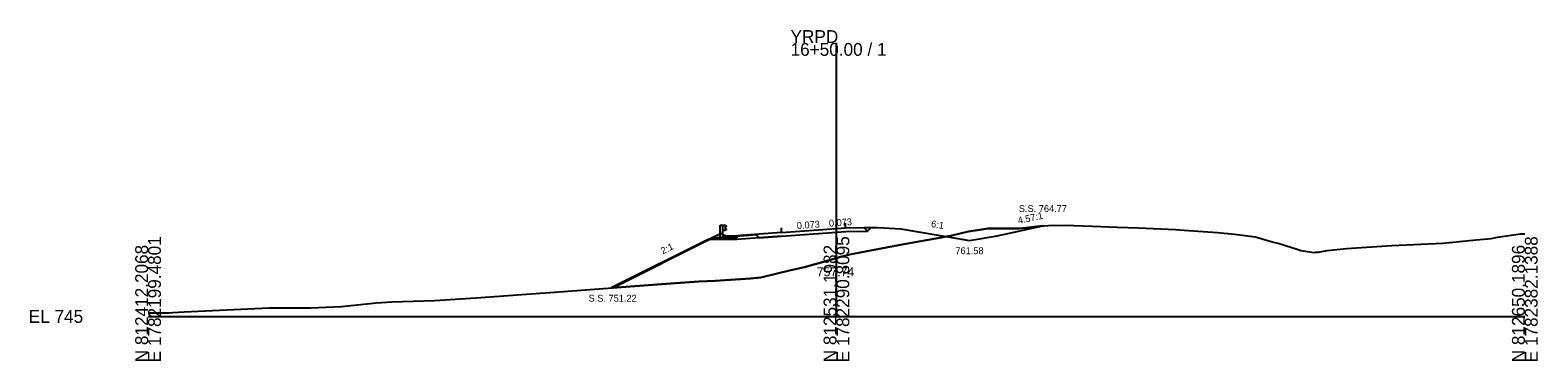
# Model space of a CAD drawing. Extents: x -26 to 1403, y -10 to 9544.
# Drawn here: x -25.7 to 302.8, y 6490.3 to 6562.4 of the extents above; entities that cross this region are included whole.
import ezdxf

# ---------------------------------------------------------------- set-up
doc = ezdxf.new("R2010")
doc.units = 0
for name, color, linetype in [('Exist Cross Section Cell', 7, 'Continuous'), ('Exist XS Center Line Elevation Label', 7, 'Continuous'), ('Exist XS Ground Line', 7, 'Continuous'), ('Prop XS Ditch Slope Text', 7, 'Continuous'), ('Prop XS Ditch Standard Text', 7, 'Continuous'), ('Prop XS Dump Level', 7, 'Continuous'), ('Prop XS Earthwork Shape', 7, 'Continuous'), ('Prop XS EOT Tick Mark', 7, 'Continuous'), ('Prop XS Finish Grade', 7, 'Continuous'), ('Prop XS Finish Grade CurbGutter', 7, 'Continuous'), ('Prop XS Finish Grade Earthwork', 7, 'Continuous'), ('Prop XS Finish Grade Paved Shoulder', 7, 'Continuous'), ('Prop XS Finish Grade Pavement', 7, 'Continuous'), ('Prop XS Guardrail', 7, 'Continuous'), ('Prop XS Pvmt Edge Slope', 7, 'Continuous'), ('Prop XS SE Text', 7, 'Continuous'), ('Prop XS Side Slope Text', 7, 'Continuous'), ('Prop XS SS Elevation Text', 7, 'Continuous'), ('Prop XS Subgrade CurbGutter', 7, 'Continuous'), ('Prop XS Subgrade Earthwork', 7, 'Continuous')]:
    doc.layers.add(name, color=color, linetype=linetype)

msp = doc.modelspace()

# ---------------------------------------------------------------- linework, layer by layer
at = {"layer": 'Exist Cross Section Cell'}
for p, q in [((150, 6500), (150, 6559.64)), ((0, 6500), (150, 6500)), ((150, 6500), (300, 6500))]:
    msp.add_line(p, q, dxfattribs=at)
at = {"layer": 'Exist XS Ground Line'}
for p, q in [((175.14, 6517.65), (178.79, 6518.55)), ((178.79, 6518.55), (181.71, 6518.99)), ((181.71, 6518.99), (183.02, 6519.2)), ((183.02, 6519.2), (188.84, 6519.19)), ((188.84, 6519.19), (189.82, 6519.21)), ((189.82, 6519.21), (190.64, 6519.27)), ((190.64, 6519.27), (195.21, 6519.79)), ((195.21, 6519.79), (196.23, 6519.81)), ((196.23, 6519.81), (199.73, 6519.88)), ((199.73, 6519.88), (205.83, 6519.68)), ((205.83, 6519.68), (211.19, 6519.49)), ((211.19, 6519.49), (215.84, 6519.29)), ((215.84, 6519.29), (223.87, 6518.96)), ((223.87, 6518.96), (224.75, 6518.9)), ((224.75, 6518.9), (227.83, 6518.69)), ((227.83, 6518.69), (233.06, 6518.29)), ((233.06, 6518.29), (236.75, 6517.91)), ((154.78, 6513.89), (164.35, 6515.71)), ((164.35, 6515.71), (173.7, 6517.35)), ((173.7, 6517.35), (175.14, 6517.65)), ((236.75, 6517.91), (241.29, 6517.36)), ((241.29, 6517.36), (244.96, 6516.27)), ((244.96, 6516.27), (246.46, 6515.94)), ((246.46, 6515.94), (250.4, 6514.65)), ((256.91, 6514.38), (261.14, 6514.82)), ((261.14, 6514.82), (271.01, 6515.46)), ((271.01, 6515.46), (282.12, 6515.99)), ((282.12, 6515.99), (289.37, 6516.69)), ((289.37, 6516.69), (292.66, 6516.99)), ((292.66, 6516.99), (294.07, 6517.26)), ((294.07, 6517.26), (299.04, 6517.99)), ((299.04, 6517.99), (300, 6518.02)), ((143.01, 6510.78), (150, 6512.74)), ((150, 6512.74), (150.89, 6512.98)), ((150.89, 6512.98), (152.9, 6513.53)), ((152.9, 6513.53), (154.78, 6513.89)), ((250.4, 6514.65), (251.21, 6514.39)), ((251.21, 6514.39), (254.11, 6513.98)), ((254.11, 6513.98), (254.42, 6514.03)), ((254.42, 6514.03), (254.96, 6514.01)), ((254.96, 6514.01), (256.91, 6514.38)), ((123.57, 6507.79), (131.28, 6508.26)), ((131.28, 6508.26), (133.5, 6508.52)), ((133.5, 6508.52), (140.04, 6510.06)), ((140.04, 6510.06), (143.01, 6510.78)), ((82.43, 6504.83), (84.58, 6504.99)), ((84.58, 6504.99), (85.34, 6505.04)), ((85.34, 6505.04), (86.62, 6505.15)), ((86.62, 6505.15), (112.9, 6507.13)), ((112.9, 6507.13), (119.99, 6507.63)), ((119.99, 6507.63), (123.57, 6507.79)), ((7.84, 6500.97), (26.42, 6501.87)), ((26.42, 6501.87), (35.5, 6501.86)), ((35.5, 6501.86), (42.13, 6502.15)), ((42.13, 6502.15), (49.68, 6503)), ((49.68, 6503), (53.15, 6503.16)), ((53.15, 6503.16), (62.38, 6503.46)), ((62.38, 6503.46), (71.53, 6504.06)), ((71.53, 6504.06), (82.43, 6504.83)), ((0, 6500.8), (3.61, 6500.81)), ((3.61, 6500.81), (4.42, 6500.78)), ((4.42, 6500.78), (5.37, 6500.85)), ((5.37, 6500.85), (7.84, 6500.97))]:
    msp.add_line(p, q, dxfattribs=at)
at = {"layer": 'Prop XS Dump Level'}
for p, q in [((138, 6518.29), (150, 6519.17)), ((150, 6519.17), (152, 6519.32))]:
    msp.add_line(p, q, dxfattribs=at)
at = {"layer": 'Prop XS Earthwork Shape'}
for points in [[(152.03, 6518.53), (156.78, 6518.59), (157.58, 6519.4), (159, 6519.41), (164, 6519.08), (174, 6517.41), (173.7, 6517.35), (164.35, 6515.71), (154.78, 6513.89), (152.9, 6513.53), (150.89, 6512.98), (150, 6512.74), (143.01, 6510.78), (140.04, 6510.06), (133.5, 6508.52), (131.28, 6508.26), (123.57, 6507.79), (119.99, 6507.63), (112.9, 6507.13), (101.26, 6506.25), (123, 6517.12), (131, 6517.76), (132.41, 6517.87), (133.14, 6517.14), (138.06, 6517.5), (150.06, 6518.38)], [(185, 6517.58), (195, 6519.77), (190.64, 6519.27), (189.82, 6519.21), (188.84, 6519.19), (183.02, 6519.2), (181.71, 6518.99), (178.79, 6518.55), (175.14, 6517.65), (174, 6517.41), (179, 6516.58)]]:
    msp.add_lwpolyline(points, close=True, dxfattribs=at)
at = {"layer": 'Prop XS EOT Tick Mark'}
for p, q in [((138, 6518.29), (138, 6519.29)), ((152, 6519.32), (152, 6520.32))]:
    msp.add_line(p, q, dxfattribs=at)
at = {"layer": 'Prop XS Finish Grade'}
for p, q in [((122.07, 6516.79), (124.73, 6518.12)), ((125.31, 6517.83), (124.73, 6518.12)), ((156, 6519.37), (157.58, 6519.4))]:
    msp.add_line(p, q, dxfattribs=at)
at = {"layer": 'Prop XS Finish Grade CurbGutter'}
for p, q in [((126, 6517.49), (125.31, 6517.83)), ((128.33, 6517.59), (126, 6517.49))]:
    msp.add_line(p, q, dxfattribs=at)
at = {"layer": 'Prop XS Finish Grade Earthwork'}
for p, q in [((157.58, 6519.4), (159, 6519.41)), ((159, 6519.41), (164, 6519.08)), ((164, 6519.08), (179, 6516.58)), ((185, 6517.58), (195, 6519.77)), ((122.07, 6516.79), (100.93, 6506.22)), ((179, 6516.58), (185, 6517.58))]:
    msp.add_line(p, q, dxfattribs=at)
at = {"layer": 'Prop XS Finish Grade Paved Shoulder'}
for p, q in [((138, 6518.29), (128.33, 6517.59)), ((152, 6519.32), (156, 6519.37))]:
    msp.add_line(p, q, dxfattribs=at)
at = {"layer": 'Prop XS Finish Grade Pavement'}
for p, q in [((138, 6518.29), (150, 6519.17)), ((150, 6519.17), (152, 6519.32))]:
    msp.add_line(p, q, dxfattribs=at)
at = {"layer": 'Prop XS Guardrail'}
for p, q in [((124.68, 6519.89), (125.18, 6519.89)), ((124.68, 6517.39), (124.68, 6519.89)), ((125.18, 6519.89), (125.68, 6519.89)), ((125.18, 6519.89), (125.18, 6517.39)), ((125.68, 6518.75), (125.18, 6518.75)), ((125.68, 6519.89), (125.97, 6519.69)), ((125.97, 6519.57), (125.68, 6519.37)), ((125.68, 6519.37), (125.68, 6519.27)), ((125.68, 6519.27), (125.97, 6519.07)), ((125.97, 6518.95), (125.68, 6518.75)), ((125.97, 6519.69), (126, 6519.63)), ((126, 6519.63), (125.97, 6519.57)), ((125.97, 6519.07), (126, 6519.01)), ((126, 6519.01), (125.97, 6518.95))]:
    msp.add_line(p, q, dxfattribs=at)
at = {"layer": 'Prop XS Pvmt Edge Slope'}
for p, q in [((156, 6519.37), (156.78, 6518.59)), ((124.31, 6517.17), (123.94, 6516.79)), ((125.31, 6517.17), (124.31, 6517.17))]:
    msp.add_line(p, q, dxfattribs=at)
at = {"layer": 'Prop XS Subgrade CurbGutter'}
for p, q in [((125.31, 6517.17), (125.31, 6517.83)), ((128.33, 6517.17), (125.31, 6517.17)), ((128.33, 6517.59), (128.33, 6517.17))]:
    msp.add_line(p, q, dxfattribs=at)
at = {"layer": 'Prop XS Subgrade Earthwork'}
for p, q in [((138.06, 6517.5), (150.06, 6518.38)), ((150.06, 6518.38), (152.03, 6518.53)), ((152.03, 6518.53), (156.78, 6518.59)), ((156.78, 6518.59), (157.58, 6519.4)), ((123.94, 6516.79), (122.07, 6516.79)), ((128.33, 6516.79), (123.94, 6516.79)), ((138, 6517.5), (128.33, 6516.79)), ((128.33, 6516.79), (128.33, 6516.79))]:
    msp.add_line(p, q, dxfattribs=at)

# ---------------------------------------------------------------- texts
at = {"layer": 'Exist Cross Section Cell'}
for s, p in [('YRPD', (140, 6559.64)), ('16+50.00 / 1', (140, 6556.84)), ('EL 745', (-26, 6498.6))]:
    msp.add_text(s, height=2.8, dxfattribs=at).set_placement(p)
for s, p in [('N 812412.2068', (0, 6490)), ('E 1782199.4801', (2.8, 6490)), ('N 812531.1982', (150, 6490)), ('E 1782290.8095', (152.8, 6490)), ('N 812650.1896', (300, 6490)), ('E 1782382.1388', (302.8, 6490))]:
    msp.add_text(s, height=2.8, rotation=90, dxfattribs=at).set_placement(p)
at = {"layer": 'Exist XS Center Line Elevation Label'}
msp.add_text('757.74', height=2, dxfattribs=at).set_placement((145.72, 6508.74))
at = {"layer": 'Prop XS Ditch Slope Text'}
msp.add_text('6:1', height=1.5, rotation=350.5377, dxfattribs=at).set_placement((170.55, 6519.51))
at = {"layer": 'Prop XS Ditch Standard Text'}
msp.add_text('761.58', height=1.5, dxfattribs=at).set_placement((175.92, 6513.58))
at = {"layer": 'Prop XS Dump Level'}
for s, p in [('Case4', (164, 6519.04)), ('Case4', (126, 6517.32)), ('Case2', (128.33, 6517.55))]:
    msp.add_text(s, height=0.04, dxfattribs=at).set_placement(p)
at = {"layer": 'Prop XS SE Text'}
for p in [(148.42, 6519.56), (141.42, 6519.04)]:
    msp.add_text('0.073', height=1.5, rotation=4.1957, dxfattribs=at).set_placement(p)
at = {"layer": 'Prop XS Side Slope Text'}
for s, rotation, p in [('4.57:1', 12.3315, (189.68, 6520.14)), ('2:1', 26.5651, (112.16, 6513.51))]:
    msp.add_text(s, height=1.5, rotation=rotation, dxfattribs=at).set_placement(p)
at = {"layer": 'Prop XS SS Elevation Text'}
for s, p in [('S.S. 764.77', (189.74, 6522.77)), ('S.S. 751.22', (95.99, 6503.22))]:
    msp.add_text(s, height=1.5, dxfattribs=at).set_placement(p)

doc.saveas('drawing.dxf')
